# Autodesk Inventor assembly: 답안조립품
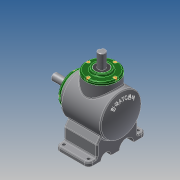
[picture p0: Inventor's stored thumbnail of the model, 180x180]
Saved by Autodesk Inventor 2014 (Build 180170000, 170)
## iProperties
Created: 2018-08
Part Number: 답안조립품
Document SubType Name: Assembly
Designer: kb542-19
Author: kb542-19
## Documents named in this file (14)
- C:\Users\kb542-19\Desktop\최형교\답안조립품.iam
- C:\Users\kb542-19\Desktop\최형교\본체.ipt
- C:\Users\kb542-19\Desktop\최형교\메인 베벨기어.ipt
- C:\Users\kb542-19\Desktop\최형교\메인 축.ipt
- 메인 축.ipt
- C:\Users\kb542-19\Desktop\최형교\베어링 6203.ipt
- C:\Users\kb542-19\Desktop\최형교\볼트 M4.ipt
- C:\Users\kb542-19\Desktop\최형교\서브 베벨기어.ipt
- C:\Users\kb542-19\Desktop\최형교\서브 축.ipt
- 서브 축.ipt
- C:\Users\kb542-19\Desktop\최형교\오일실 17 32 8.ipt
- C:\Users\kb542-19\Desktop\최형교\커버.ipt
- C:\Users\kb542-19\Desktop\최형교\키 4x4.ipt
- C:\Users\kb542-19\Desktop\최형교\키 5x5.ipt
